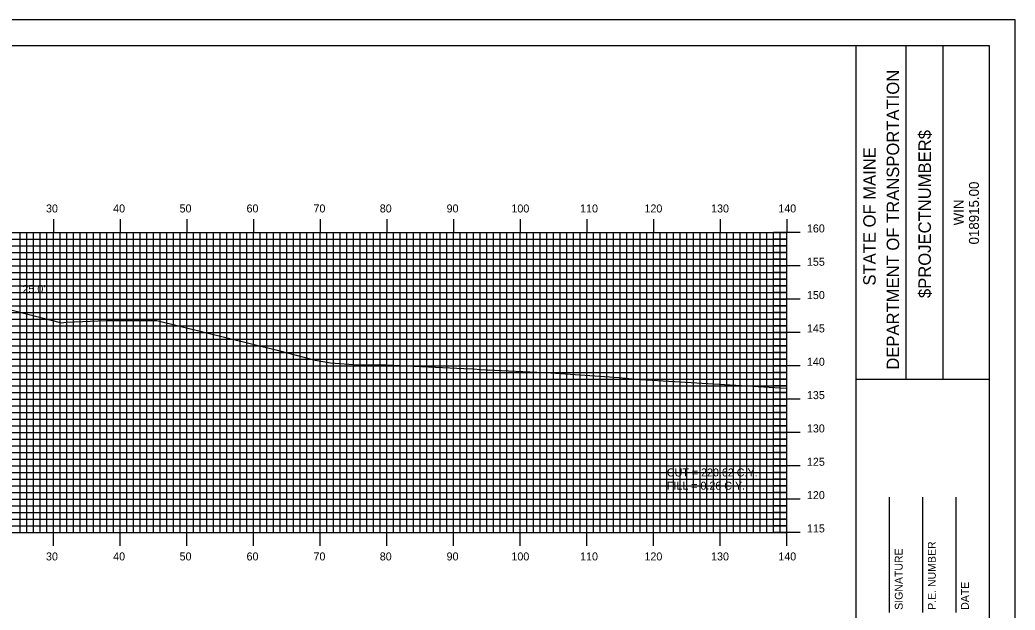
# Model space of a CAD drawing. Extents: x 860652 to 860995, y 364765 to 364985.
# Drawn here: x 860842.4 to 860991.6, y 364896.6 to 364985.2 of the extents above; entities that cross this region are included whole.
import ezdxf

# ---------------------------------------------------------------- set-up
doc = ezdxf.new("R2010")
doc.units = 0
for name, color, linetype in [('BORDER', 7, 'Continuous'), ('D_Text_Standard', 7, 'Continuous'), ('H_V ANNOTATION', 7, 'Continuous'), ('MAJOR', 7, 'Continuous'), ('MINOR', 7, 'Continuous'), ('PLOT BOUNDARY', 7, 'Continuous'), ('S_Roadway_Centerline', 7, 'Continuous')]:
    doc.layers.add(name, color=color, linetype=linetype)

msp = doc.modelspace()

# ---------------------------------------------------------------- linework, layer by layer
at = {"layer": 'BORDER'}
for p, q in [((860967.81, 364771.3), (860967.81, 364981.3)), ((860975.27, 364931.3), (860975.27, 364981.3)), ((860980.86, 364931.3), (860980.86, 364981.3)), ((860967.81, 364931.29), (860987.81, 364931.29)), ((860972.81, 364896.31), (860972.81, 364913.6)), ((860977.81, 364896.31), (860977.81, 364913.6)), ((860982.81, 364896.31), (860982.81, 364913.6))]:
    msp.add_line(p, q, dxfattribs=at)
msp.add_lwpolyline([(860667.81, 364771.3), (860987.81, 364771.3), (860987.81, 364981.3), (860667.81, 364981.3)], close=True, dxfattribs=at)
at = {"layer": 'MAJOR'}
for p, q in [((860847.41, 364955.31), (860847.41, 364953.3)), ((860857.41, 364955.31), (860857.41, 364953.3)), ((860867.41, 364955.31), (860867.41, 364953.3)), ((860877.41, 364955.31), (860877.41, 364953.3)), ((860887.41, 364955.31), (860887.41, 364953.3)), ((860897.41, 364955.31), (860897.41, 364953.3)), ((860907.41, 364955.31), (860907.41, 364953.3)), ((860917.41, 364955.31), (860917.41, 364953.3)), ((860927.41, 364955.31), (860927.41, 364953.3)), ((860937.41, 364955.31), (860937.41, 364953.3)), ((860947.41, 364955.31), (860947.41, 364953.3)), ((860957.41, 364955.31), (860957.41, 364953.3)), ((860677.41, 364953.3), (860957.41, 364953.3)), ((860677.41, 364953.3), (860957.41, 364953.3)), ((860847.41, 364908.3), (860847.41, 364953.3)), ((860857.41, 364908.3), (860857.41, 364953.3)), ((860867.41, 364908.3), (860867.41, 364953.3)), ((860877.41, 364908.3), (860877.41, 364953.3)), ((860887.41, 364908.3), (860887.41, 364953.3)), ((860897.41, 364908.3), (860897.41, 364953.3)), ((860907.41, 364908.3), (860907.41, 364953.3)), ((860917.41, 364908.3), (860917.41, 364953.3)), ((860927.41, 364908.3), (860927.41, 364953.3)), ((860937.41, 364908.3), (860937.41, 364953.3)), ((860947.41, 364908.3), (860947.41, 364953.3)), ((860959.42, 364953.3), (860955.41, 364953.3)), ((860957.41, 364908.3), (860957.41, 364953.3)), ((860957.41, 364908.3), (860957.41, 364953.3)), ((860677.41, 364948.3), (860957.41, 364948.3)), ((860959.42, 364948.3), (860955.41, 364948.3)), ((860677.41, 364943.3), (860957.41, 364943.3)), ((860959.42, 364943.3), (860955.41, 364943.3)), ((860677.41, 364938.3), (860957.41, 364938.3)), ((860959.42, 364938.3), (860955.41, 364938.3)), ((860677.41, 364933.3), (860957.41, 364933.3)), ((860959.42, 364933.3), (860955.41, 364933.3)), ((860677.41, 364928.3), (860957.41, 364928.3)), ((860959.42, 364928.3), (860955.41, 364928.3)), ((860677.41, 364923.3), (860957.41, 364923.3)), ((860959.42, 364923.3), (860955.41, 364923.3)), ((860677.41, 364918.3), (860957.41, 364918.3)), ((860959.42, 364918.3), (860955.41, 364918.3)), ((860677.41, 364913.3), (860957.41, 364913.3)), ((860959.42, 364913.3), (860955.41, 364913.3)), ((860677.41, 364908.3), (860957.41, 364908.3)), ((860677.41, 364908.3), (860957.41, 364908.3)), ((860847.41, 364906.3), (860847.41, 364908.3)), ((860857.41, 364906.3), (860857.41, 364908.3)), ((860867.41, 364906.3), (860867.41, 364908.3)), ((860877.41, 364906.3), (860877.41, 364908.3)), ((860887.41, 364906.3), (860887.41, 364908.3)), ((860897.41, 364906.3), (860897.41, 364908.3)), ((860907.41, 364906.3), (860907.41, 364908.3)), ((860917.41, 364906.3), (860917.41, 364908.3)), ((860927.41, 364906.3), (860927.41, 364908.3)), ((860937.41, 364906.3), (860937.41, 364908.3)), ((860947.41, 364906.3), (860947.41, 364908.3)), ((860959.42, 364908.3), (860955.41, 364908.3)), ((860957.41, 364906.3), (860957.41, 364908.3))]:
    msp.add_line(p, q, dxfattribs=at)
at = {"layer": 'MINOR'}
for p, q in [((860842.41, 364908.3), (860842.41, 364953.3)), ((860843.41, 364908.3), (860843.41, 364953.3)), ((860844.41, 364908.3), (860844.41, 364953.3)), ((860845.41, 364908.3), (860845.41, 364953.3)), ((860846.41, 364908.3), (860846.41, 364953.3)), ((860848.41, 364908.3), (860848.41, 364953.3)), ((860849.41, 364908.3), (860849.41, 364953.3)), ((860850.41, 364908.3), (860850.41, 364953.3)), ((860851.41, 364908.3), (860851.41, 364953.3)), ((860852.41, 364908.3), (860852.41, 364953.3)), ((860853.41, 364908.3), (860853.41, 364953.3)), ((860854.41, 364908.3), (860854.41, 364953.3)), ((860855.41, 364908.3), (860855.41, 364953.3)), ((860856.41, 364908.3), (860856.41, 364953.3)), ((860858.41, 364908.3), (860858.41, 364953.3)), ((860859.41, 364908.3), (860859.41, 364953.3)), ((860860.41, 364908.3), (860860.41, 364953.3)), ((860861.41, 364908.3), (860861.41, 364953.3)), ((860862.41, 364908.3), (860862.41, 364953.3)), ((860863.41, 364908.3), (860863.41, 364953.3)), ((860864.41, 364908.3), (860864.41, 364953.3)), ((860865.41, 364908.3), (860865.41, 364953.3)), ((860866.41, 364908.3), (860866.41, 364953.3)), ((860868.41, 364908.3), (860868.41, 364953.3)), ((860869.41, 364908.3), (860869.41, 364953.3)), ((860870.41, 364908.3), (860870.41, 364953.3)), ((860871.41, 364908.3), (860871.41, 364953.3)), ((860872.41, 364908.3), (860872.41, 364953.3)), ((860873.41, 364908.3), (860873.41, 364953.3)), ((860874.41, 364908.3), (860874.41, 364953.3)), ((860875.41, 364908.3), (860875.41, 364953.3)), ((860876.41, 364908.3), (860876.41, 364953.3)), ((860878.41, 364908.3), (860878.41, 364953.3)), ((860879.41, 364908.3), (860879.41, 364953.3)), ((860880.41, 364908.3), (860880.41, 364953.3)), ((860881.41, 364908.3), (860881.41, 364953.3)), ((860882.41, 364908.3), (860882.41, 364953.3)), ((860883.41, 364908.3), (860883.41, 364953.3)), ((860884.41, 364908.3), (860884.41, 364953.3)), ((860885.41, 364908.3), (860885.41, 364953.3)), ((860886.41, 364908.3), (860886.41, 364953.3)), ((860888.41, 364908.3), (860888.41, 364953.3)), ((860889.41, 364908.3), (860889.41, 364953.3)), ((860890.41, 364908.3), (860890.41, 364953.3)), ((860891.41, 364908.3), (860891.41, 364953.3)), ((860892.41, 364908.3), (860892.41, 364953.3)), ((860893.41, 364908.3), (860893.41, 364953.3)), ((860894.41, 364908.3), (860894.41, 364953.3)), ((860895.41, 364908.3), (860895.41, 364953.3)), ((860896.41, 364908.3), (860896.41, 364953.3)), ((860898.41, 364908.3), (860898.41, 364953.3)), ((860899.41, 364908.3), (860899.41, 364953.3)), ((860900.41, 364908.3), (860900.41, 364953.3)), ((860901.41, 364908.3), (860901.41, 364953.3)), ((860902.41, 364908.3), (860902.41, 364953.3)), ((860903.41, 364908.3), (860903.41, 364953.3)), ((860904.41, 364908.3), (860904.41, 364953.3)), ((860905.41, 364908.3), (860905.41, 364953.3)), ((860906.41, 364908.3), (860906.41, 364953.3)), ((860908.41, 364908.3), (860908.41, 364953.3)), ((860909.41, 364908.3), (860909.41, 364953.3)), ((860910.41, 364908.3), (860910.41, 364953.3)), ((860911.41, 364908.3), (860911.41, 364953.3)), ((860912.41, 364908.3), (860912.41, 364953.3)), ((860913.41, 364908.3), (860913.41, 364953.3)), ((860914.41, 364908.3), (860914.41, 364953.3)), ((860915.41, 364908.3), (860915.41, 364953.3)), ((860916.41, 364908.3), (860916.41, 364953.3)), ((860918.41, 364908.3), (860918.41, 364953.3)), ((860919.41, 364908.3), (860919.41, 364953.3)), ((860920.41, 364908.3), (860920.41, 364953.3)), ((860921.41, 364908.3), (860921.41, 364953.3)), ((860922.41, 364908.3), (860922.41, 364953.3)), ((860923.41, 364908.3), (860923.41, 364953.3)), ((860924.41, 364908.3), (860924.41, 364953.3)), ((860925.41, 364908.3), (860925.41, 364953.3)), ((860926.41, 364908.3), (860926.41, 364953.3)), ((860928.41, 364908.3), (860928.41, 364953.3)), ((860929.41, 364908.3), (860929.41, 364953.3)), ((860930.41, 364908.3), (860930.41, 364953.3)), ((860931.41, 364908.3), (860931.41, 364953.3)), ((860932.41, 364908.3), (860932.41, 364953.3)), ((860933.41, 364908.3), (860933.41, 364953.3)), ((860934.41, 364908.3), (860934.41, 364953.3)), ((860935.41, 364908.3), (860935.41, 364953.3)), ((860936.41, 364908.3), (860936.41, 364953.3)), ((860938.41, 364908.3), (860938.41, 364953.3)), ((860939.41, 364908.3), (860939.41, 364953.3)), ((860940.41, 364908.3), (860940.41, 364953.3)), ((860941.41, 364908.3), (860941.41, 364953.3)), ((860942.41, 364908.3), (860942.41, 364953.3)), ((860943.41, 364908.3), (860943.41, 364953.3)), ((860944.41, 364908.3), (860944.41, 364953.3)), ((860945.41, 364908.3), (860945.41, 364953.3)), ((860946.41, 364908.3), (860946.41, 364953.3)), ((860948.41, 364908.3), (860948.41, 364953.3)), ((860949.41, 364908.3), (860949.41, 364953.3)), ((860950.41, 364908.3), (860950.41, 364953.3)), ((860951.41, 364908.3), (860951.41, 364953.3)), ((860952.41, 364908.3), (860952.41, 364953.3)), ((860953.41, 364908.3), (860953.41, 364953.3)), ((860954.41, 364908.3), (860954.41, 364953.3)), ((860955.41, 364908.3), (860955.41, 364953.3)), ((860956.41, 364908.3), (860956.41, 364953.3)), ((860677.41, 364952.3), (860957.41, 364952.3)), ((860677.41, 364951.3), (860957.41, 364951.3)), ((860957.41, 364952.3), (860955.41, 364952.3)), ((860957.41, 364951.3), (860955.41, 364951.3)), ((860677.41, 364950.3), (860957.41, 364950.3)), ((860957.41, 364950.3), (860955.41, 364950.3)), ((860677.41, 364949.3), (860957.41, 364949.3)), ((860957.41, 364949.3), (860955.41, 364949.3)), ((860677.41, 364947.3), (860957.41, 364947.3)), ((860957.41, 364947.3), (860955.41, 364947.3)), ((860677.41, 364946.3), (860957.41, 364946.3)), ((860677.41, 364945.3), (860957.41, 364945.3)), ((860957.41, 364946.3), (860955.41, 364946.3)), ((860957.41, 364945.3), (860955.41, 364945.3)), ((860677.41, 364944.3), (860957.41, 364944.3)), ((860957.41, 364944.3), (860955.41, 364944.3)), ((860677.41, 364942.3), (860957.41, 364942.3)), ((860957.41, 364942.3), (860955.41, 364942.3)), ((860677.41, 364941.3), (860957.41, 364941.3)), ((860957.41, 364941.3), (860955.41, 364941.3)), ((860677.41, 364940.3), (860957.41, 364940.3)), ((860677.41, 364939.3), (860957.41, 364939.3)), ((860957.41, 364940.3), (860955.41, 364940.3)), ((860957.41, 364939.3), (860955.41, 364939.3)), ((860677.41, 364937.3), (860957.41, 364937.3)), ((860677.41, 364936.3), (860957.41, 364936.3)), ((860957.41, 364937.3), (860955.41, 364937.3)), ((860957.41, 364936.3), (860955.41, 364936.3)), ((860677.41, 364935.3), (860957.41, 364935.3)), ((860957.41, 364935.3), (860955.41, 364935.3)), ((860677.41, 364934.3), (860957.41, 364934.3)), ((860957.41, 364934.3), (860955.41, 364934.3)), ((860677.41, 364932.3), (860957.41, 364932.3)), ((860957.41, 364932.3), (860955.41, 364932.3)), ((860677.41, 364931.3), (860957.41, 364931.3)), ((860677.41, 364930.3), (860957.41, 364930.3)), ((860957.41, 364931.3), (860955.41, 364931.3)), ((860957.41, 364930.3), (860955.41, 364930.3)), ((860677.41, 364929.3), (860957.41, 364929.3)), ((860957.41, 364929.3), (860955.41, 364929.3)), ((860677.41, 364927.3), (860957.41, 364927.3)), ((860957.41, 364927.3), (860955.41, 364927.3)), ((860677.41, 364926.3), (860957.41, 364926.3)), ((860957.41, 364926.3), (860955.41, 364926.3)), ((860677.41, 364925.3), (860957.41, 364925.3)), ((860677.41, 364924.3), (860957.41, 364924.3)), ((860957.41, 364925.3), (860955.41, 364925.3)), ((860957.41, 364924.3), (860955.41, 364924.3)), ((860677.41, 364922.3), (860957.41, 364922.3)), ((860677.41, 364921.3), (860957.41, 364921.3)), ((860957.41, 364922.3), (860955.41, 364922.3)), ((860957.41, 364921.3), (860955.41, 364921.3)), ((860677.41, 364920.3), (860957.41, 364920.3)), ((860957.41, 364920.3), (860955.41, 364920.3)), ((860677.41, 364919.3), (860957.41, 364919.3)), ((860957.41, 364919.3), (860955.41, 364919.3)), ((860677.41, 364917.3), (860957.41, 364917.3)), ((860957.41, 364917.3), (860955.41, 364917.3)), ((860677.41, 364916.3), (860957.41, 364916.3)), ((860677.41, 364915.3), (860957.41, 364915.3)), ((860957.41, 364916.3), (860955.41, 364916.3)), ((860957.41, 364915.3), (860955.41, 364915.3)), ((860677.41, 364914.3), (860957.41, 364914.3)), ((860957.41, 364914.3), (860955.41, 364914.3)), ((860677.41, 364912.3), (860957.41, 364912.3)), ((860957.41, 364912.3), (860955.41, 364912.3)), ((860677.41, 364911.3), (860957.41, 364911.3)), ((860957.41, 364911.3), (860955.41, 364911.3)), ((860677.41, 364910.3), (860957.41, 364910.3)), ((860677.41, 364909.3), (860957.41, 364909.3)), ((860957.41, 364910.3), (860955.41, 364910.3)), ((860957.41, 364909.3), (860955.41, 364909.3))]:
    msp.add_line(p, q, dxfattribs=at)
at = {"layer": 'PLOT BOUNDARY'}
msp.add_lwpolyline([(860651.63, 364765.18), (860991.63, 364765.18), (860991.63, 364985.18), (860651.63, 364985.18)], close=True, dxfattribs=at)
at = {"layer": 'S_Roadway_Centerline'}
msp.add_lwpolyline([(860837.07, 364942.67), (860847.48, 364940.05), (860848.59, 364939.72), (860849.37, 364939.85), (860855.35, 364940.08), (860862.92, 364940.09), (860880.76, 364935.67), (860886.69, 364934.15), (860888.97, 364933.76), (860893.11, 364933.42), (860894.13, 364933.42), (860896.21, 364933.47), (860908.94, 364932.87), (860910.41, 364932.82), (860911.45, 364932.75), (860922.02, 364932.22), (860932.24, 364931.52), (860933.23, 364931.45), (860933.68, 364931.38), (860934.22, 364931.33), (860935.52, 364931.22), (860953.11, 364930.19), (860956.4, 364929.97), (860957.41, 364929.96)], dxfattribs=at)

# ---------------------------------------------------------------- texts
at = {"layer": 'BORDER'}
for s, height, p in [('DEPARTMENT OF TRANSPORTATION', 1.8635, (860974.23, 364932.71)), ('$PROJECTNUMBER$', 1.8635, (860979, 364943.46)), ('STATE OF MAINE', 1.8635, (860970.72, 364945.33)), ('018915.00', 1.491, (860986.2, 364951.5)), ('WIN', 1.491, (860983.89, 364954.36)), ('P.E. NUMBER', 1.1811, (860979.73, 364896.69)), ('SIGNATURE', 1.181, (860974.77, 364896.69)), ('DATE', 1.181, (860984.69, 364896.69))]:
    msp.add_text(s, height=height, rotation=90, dxfattribs=at).set_placement(p)
at = {"layer": 'D_Text_Standard'}
for s, p in [("25.0'", (860842.78, 364944.22)), ('CUT = 220.62 C.Y.', (860939.41, 364916.7)), ('FILL = 0.26 C.Y.', (860939.41, 364914.71))]:
    msp.add_text(s, height=1.2, dxfattribs=at).set_placement(p)
at = {"layer": 'H_V ANNOTATION'}
for s, p in [('30', (860846.31, 364956.3)), ('40', (860856.38, 364956.3)), ('50', (860866.34, 364956.3)), ('60', (860876.38, 364956.3)), ('70', (860886.42, 364956.3)), ('80', (860896.36, 364956.3)), ('90', (860906.38, 364956.3)), ('100', (860916.1, 364956.3)), ('110', (860926.4, 364956.3)), ('120', (860936.05, 364956.3)), ('130', (860946.04, 364956.3)), ('140', (860956.12, 364956.3)), ('160', (860960.41, 364953.3)), ('155', (860960.41, 364948.3)), ('150', (860960.41, 364943.3)), ('145', (860960.41, 364938.3)), ('140', (860960.41, 364933.3)), ('135', (860960.41, 364928.3)), ('130', (860960.41, 364923.3)), ('125', (860960.41, 364918.3)), ('120', (860960.41, 364913.3)), ('115', (860960.41, 364908.3)), ('30', (860846.31, 364904.1)), ('40', (860856.38, 364904.1)), ('50', (860866.34, 364904.1)), ('60', (860876.38, 364904.1)), ('70', (860886.42, 364904.1)), ('80', (860896.36, 364904.1)), ('90', (860906.38, 364904.1)), ('100', (860916.1, 364904.1)), ('110', (860926.4, 364904.1)), ('120', (860936.05, 364904.1)), ('130', (860946.04, 364904.1)), ('140', (860956.12, 364904.1))]:
    msp.add_text(s, height=1.2, dxfattribs=at).set_placement(p)

doc.saveas('drawing.dxf')
